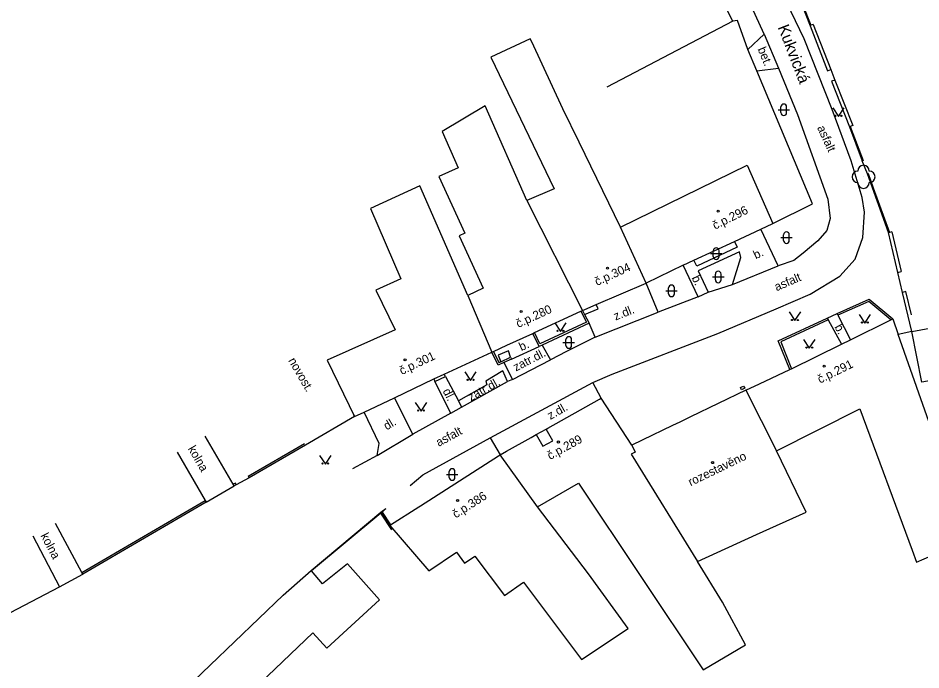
# Model space of a CAD drawing. Extents: x -577457 to -568404, y -1208466 to -1201387.
# Drawn here: x -573550.3 to -573471.9, y -1206438 to -1206381.4 of the extents above; entities that cross this region are included whole.
import ezdxf

# ---------------------------------------------------------------- set-up
doc = ezdxf.new("R2010")
doc.units = 0
for name, color, linetype in [('BUDOVY_MĚŘ', 7, 'Continuous'), ('BUDOVY_NEMĚŘ', 7, 'Continuous'), ('NÁZVY_ULIC_TOK_SMĚR', 7, 'Continuous'), ('OBVOD_PILÍŘE', 7, 'Continuous'), ('POMOC_POPIS', 7, 'Continuous'), ('ROZHRANÍ_PLOCH', 7, 'Continuous'), ('ZELEŇ', 7, 'Continuous'), ('ZN_BUDOV', 7, 'Continuous'), ('ZN_DOPLŇKOVÉ', 7, 'Continuous'), ('ZN_KULTUR', 7, 'Continuous'), ('Č_POPIS_ORIENT', 7, 'Continuous')]:
    doc.layers.add(name, color=color, linetype=linetype)

msp = doc.modelspace()

# ---------------------------------------------------------------- linework, layer by layer
at = {"layer": 'BUDOVY_MĚŘ'}
for points in [[(-573485.78, -1206399.68), (-573484.76, -1206399.2)], [(-573491.61, -1206402.38), (-573488.08, -1206400.76)], [(-573492.54, -1206402.83), (-573495.76, -1206404.39)], [(-573500.09, -1206406.24), (-573495.76, -1206404.39)], [(-573505.44, -1206408.67), (-573501.42, -1206406.82)], [(-573501.42, -1206406.82), (-573501.27, -1206406.75)], [(-573501.27, -1206406.75), (-573501.09, -1206406.67)], [(-573477.99, -1206409.3), (-573474.51, -1206407.57)], [(-573474.51, -1206407.57), (-573474.34, -1206407.49)], [(-573474.34, -1206407.49), (-573473.87, -1206408.83)], [(-573505.6, -1206408.74), (-573505.44, -1206408.67)], [(-573509.16, -1206410.37), (-573509.01, -1206410.3)], [(-573509.01, -1206410.3), (-573507.85, -1206409.77)], [(-573483.12, -1206411.82), (-573478.78, -1206409.69)], [(-573513.29, -1206412.28), (-573509.16, -1206410.37)], [(-573483.27, -1206411.89), (-573483.12, -1206411.82)], [(-573514.2, -1206412.7), (-573513.29, -1206412.28)], [(-573517.62, -1206414.33), (-573514.2, -1206412.7)], [(-573487.1, -1206413.66), (-573485.91, -1206413.11)], [(-573487.1, -1206413.66), (-573491.91, -1206415.98)], [(-573504.29, -1206416.97), (-573499.8, -1206414.44)], [(-573499.8, -1206414.44), (-573499.65, -1206414.36)], [(-573497, -1206418.44), (-573499.65, -1206414.36)], [(-573521.1, -1206415.97), (-573520.24, -1206415.57)], [(-573521.1, -1206415.97), (-573525.34, -1206418.44)], [(-573521.18, -1206415.81), (-573521.1, -1206415.97)], [(-573492.84, -1206416.44), (-573493.47, -1206416.74)], [(-573505.3, -1206417.53), (-573504.43, -1206417.05)], [(-573505.3, -1206417.53), (-573504.74, -1206418.54), (-573503.87, -1206418.06), (-573504.43, -1206417.05)], [(-573504.43, -1206417.05), (-573504.29, -1206416.97)], [(-573531.63, -1206421.84), (-573534.06, -1206417.66)], [(-573505.75, -1206417.78), (-573505.3, -1206417.53)], [(-573496.11, -1206418.01), (-573497, -1206418.44)], [(-573536.48, -1206419.06), (-573534.06, -1206423.24)], [(-573515.35, -1206423.71), (-573508.57, -1206419.36)], [(-573508.57, -1206419.36), (-573508.43, -1206419.27)], [(-573508.43, -1206419.27), (-573507.88, -1206418.96)], [(-573533.97, -1206423.39), (-573531.55, -1206421.98)], [(-573531.55, -1206421.98), (-573531.63, -1206421.84)], [(-573534.06, -1206423.24), (-573533.97, -1206423.39)], [(-573517.97, -1206425.37), (-573515.49, -1206423.8)], [(-573515.49, -1206423.8), (-573515.35, -1206423.71)], [(-573544.76, -1206429.49), (-573547.06, -1206425.25)], [(-573518.03, -1206425.41), (-573517.97, -1206425.37)], [(-573549.03, -1206426.31), (-573546.72, -1206430.75)], [(-573546.72, -1206430.75), (-573544.68, -1206429.64)], [(-573544.68, -1206429.64), (-573544.76, -1206429.49)], [(-573537.86, -1206441.6), (-573527.29, -1206431.47), (-573524.86, -1206429.31)], [(-573524.86, -1206429.31), (-573524.81, -1206429.36)], [(-573552.28, -1206433.52), (-573552.22, -1206433.61), (-573546.72, -1206430.75)]]:
    msp.add_lwpolyline(points, dxfattribs=at)
at = {"layer": 'BUDOVY_NEMĚŘ'}
for points in [[(-573497.97, -1206399.52), (-573501.57, -1206392.15), (-573502.99, -1206389.25), (-573505.69, -1206383.44), (-573505.82, -1206383.17), (-573509.26, -1206384.76), (-573503.74, -1206396.2), (-573506.13, -1206397.22)], [(-573506.13, -1206397.22), (-573509.74, -1206389), (-573513.48, -1206391.22), (-573512.08, -1206394.36), (-573513.76, -1206395.13), (-573511.51, -1206400.04), (-573512.01, -1206400.27), (-573509.9, -1206404.82), (-573511.24, -1206405.45)], [(-573497.97, -1206399.52), (-573486.98, -1206394.15), (-573484.76, -1206399.2)], [(-573511.24, -1206405.45), (-573515.42, -1206395.93), (-573519.71, -1206397.9), (-573517.05, -1206404), (-573519.23, -1206405), (-573517.55, -1206408.44), (-573523.47, -1206411.08)], [(-573506.13, -1206397.22), (-573501.27, -1206406.75)], [(-573495.76, -1206404.39), (-573497.97, -1206399.52)], [(-573446.25, -1206413.56), (-573446.89, -1206409.11), (-573461.2, -1206411.61), (-573461.32, -1206411.12), (-573471.82, -1206412.98), (-573472.69, -1206408.57), (-573447.18, -1206403.86), (-573442.02, -1206402.96)], [(-573511.24, -1206405.45), (-573509.16, -1206410.37)], [(-573484.44, -1206418.94), (-573477.18, -1206415.29), (-573472.66, -1206427.55), (-573472.28, -1206428.59), (-573467.61, -1206426.58), (-573473.87, -1206408.83)], [(-573523.47, -1206411.08), (-573521.1, -1206415.97)], [(-573487.1, -1206413.66), (-573484.44, -1206418.94)], [(-573497, -1206418.44), (-573496.72, -1206419.04), (-573497.05, -1206419.23), (-573491.3, -1206428.54), (-573486.17, -1206426.21), (-573481.85, -1206424.25), (-573484.44, -1206418.94)], [(-573505.2, -1206423.81), (-573508.43, -1206419.27)], [(-573505.2, -1206423.81), (-573501.64, -1206421.74), (-573490.81, -1206437.95), (-573487.13, -1206435.79), (-573489.12, -1206432.07), (-573491.3, -1206428.54)], [(-573518.03, -1206425.41), (-573514.64, -1206429.35), (-573512.24, -1206427.74), (-573511.54, -1206428.7), (-573510.64, -1206428.08), (-573508.06, -1206431.5), (-573506.41, -1206430.34), (-573501.37, -1206437.06), (-573497.33, -1206434.35), (-573500.75, -1206429.61), (-573505.2, -1206423.81)], [(-573530.07, -1206444.4), (-573531.25, -1206443.69), (-573532.36, -1206445.02), (-573533.85, -1206443.46), (-573524.72, -1206434.74), (-573523.5, -1206436.08), (-573518.91, -1206431.87), (-573521.71, -1206428.75), (-573523.86, -1206430.48), (-573524.81, -1206429.36)]]:
    msp.add_lwpolyline(points, dxfattribs=at)
at = {"layer": 'OBVOD_PILÍŘE'}
msp.add_lwpolyline([(-573487.43, -1206413.38), (-573487.29, -1206413.31), (-573487.19, -1206413.51), (-573487.48, -1206413.65), (-573487.57, -1206413.45), (-573487.43, -1206413.38)], dxfattribs=at)
at = {"layer": 'ROZHRANÍ_PLOCH'}
for points in [[(-573485.5, -1206382.76), (-573488.17, -1206376.93), (-573490.3, -1206372.55), (-573491.52, -1206369.72)], [(-573476.78, -1206398.23), (-573476.98, -1206396.94), (-573477.94, -1206393.75), (-573479.61, -1206389.32), (-573482.04, -1206383.18), (-573485.38, -1206376.18), (-573487.47, -1206370.94), (-573487.87, -1206370.34)], [(-573482.85, -1206378.62), (-573481.52, -1206382.03)], [(-573481.46, -1206382), (-573481.52, -1206382.03)], [(-573481.52, -1206382.03), (-573480, -1206385.95), (-573479.72, -1206385.84)], [(-573481.24, -1206381.92), (-573481.46, -1206382)], [(-573486.91, -1206384.11), (-573485.5, -1206382.76)], [(-573485.5, -1206382.76), (-573484.26, -1206385.73)], [(-573486.15, -1206385.96), (-573484.26, -1206385.73)], [(-573484.26, -1206385.73), (-573482.61, -1206389.74), (-573479.96, -1206397.1), (-573479.77, -1206398.76), (-573480.07, -1206399.8)], [(-573479.72, -1206385.84), (-573479.37, -1206386.75)], [(-573479.37, -1206386.75), (-573479.65, -1206386.86), (-573478.08, -1206390.81)], [(-573477.8, -1206390.69), (-573478.02, -1206390.78)], [(-573478.02, -1206390.78), (-573478.08, -1206390.81)], [(-573478.08, -1206390.81), (-573476.98, -1206393.75)], [(-573476.91, -1206393.72), (-573476.98, -1206393.75)], [(-573476.54, -1206394.88), (-573476.98, -1206393.75)], [(-573476.48, -1206394.86), (-573476.54, -1206394.88)], [(-573474.69, -1206399.99), (-573476.54, -1206394.88)], [(-573489.53, -1206408.75), (-573484.46, -1206406.62), (-573481.52, -1206405.35), (-573478.94, -1206403.76), (-573477.6, -1206402.29), (-573476.94, -1206400.42), (-573476.78, -1206398.23)], [(-573484.3, -1206402.88), (-573485.78, -1206399.68)], [(-573480.07, -1206399.8), (-573480.83, -1206400.71), (-573482.12, -1206401.79), (-573482.94, -1206402.42), (-573484.3, -1206402.88)], [(-573474.62, -1206399.97), (-573474.69, -1206399.99)], [(-573473.88, -1206403.45), (-573474.69, -1206399.99)], [(-573474.4, -1206399.92), (-573474.62, -1206399.97)], [(-573488.08, -1206400.76), (-573487.84, -1206401.27), (-573491.36, -1206402.91), (-573491.61, -1206402.38)], [(-573488.24, -1206404.51), (-573487.52, -1206402.15), (-573487.66, -1206401.66), (-573491.24, -1206403.3), (-573490.37, -1206405.16)], [(-573491.25, -1206405.56), (-573492.54, -1206402.83)], [(-573488.24, -1206404.51), (-573484.3, -1206402.88)], [(-573473.88, -1206403.45), (-573473.59, -1206403.38)], [(-573494.72, -1206406.89), (-573495.76, -1206404.39)], [(-573490.37, -1206405.16), (-573488.24, -1206404.51)], [(-573491.25, -1206405.56), (-573494.72, -1206406.89)], [(-573491.25, -1206405.56), (-573490.37, -1206405.16)], [(-573472.7, -1206407.12), (-573473.21, -1206405.11), (-573473.5, -1206405.18)], [(-573472.69, -1206408.57), (-573473.5, -1206405.18)], [(-573479.16, -1206407.02), (-573476.38, -1206405.76), (-573474.34, -1206407.49)], [(-573474.51, -1206407.57), (-573476.41, -1206405.96), (-573479.09, -1206407.17)], [(-573501.42, -1206406.82), (-573500.94, -1206407.78), (-573504.98, -1206409.65), (-573505.44, -1206408.67)], [(-573501.27, -1206406.75), (-573501.1, -1206407.09)], [(-573501.1, -1206407.09), (-573500.71, -1206407.86)], [(-573500.19, -1206409.06), (-573494.72, -1206406.89)], [(-573480.02, -1206407.41), (-573479.16, -1206407.02)], [(-573479.09, -1206407.17), (-573479.16, -1206407.02)], [(-573500.71, -1206407.86), (-573504.8, -1206409.75)], [(-573500.19, -1206409.06), (-573500.71, -1206407.86)], [(-573483.27, -1206411.89), (-573484.29, -1206409.38), (-573480.02, -1206407.41)], [(-573479.95, -1206407.56), (-573484.07, -1206409.47), (-573483.12, -1206411.82)], [(-573480.02, -1206407.41), (-573479.95, -1206407.56)], [(-573479.95, -1206407.56), (-573478.78, -1206409.69)], [(-573479.09, -1206407.17), (-573477.99, -1206409.3)], [(-573505.06, -1206409.87), (-573505.6, -1206408.74)], [(-573500.19, -1206409.06), (-573502.67, -1206410.32), (-573504.07, -1206411.04)], [(-573498.72, -1206412.28), (-573489.53, -1206408.75)], [(-573509.01, -1206410.3), (-573508.54, -1206411.28), (-573508.38, -1206411.21)], [(-573507.53, -1206410.81), (-573507.7, -1206410.26), (-573508.62, -1206410.64), (-573508.38, -1206411.21)], [(-573507.46, -1206410.97), (-573505.06, -1206409.87)], [(-573504.8, -1206409.75), (-573505.06, -1206409.87)], [(-573504.8, -1206409.75), (-573504.07, -1206411.04)], [(-573508.12, -1206411.27), (-573508.62, -1206411.5), (-573509.16, -1206410.37)], [(-573508.38, -1206411.21), (-573507.53, -1206410.81), (-573507.46, -1206410.97)], [(-573507.46, -1206410.97), (-573508.12, -1206411.27)], [(-573507.37, -1206412.75), (-573504.07, -1206411.04)], [(-573508.12, -1206411.27), (-573507.37, -1206412.75)], [(-573514.2, -1206412.7), (-573514.11, -1206412.91), (-573513.19, -1206412.49), (-573513.29, -1206412.28)], [(-573513.19, -1206412.49), (-573512.06, -1206414.59)], [(-573507.8, -1206412.92), (-573508.21, -1206412), (-573509.68, -1206412.88), (-573509.58, -1206413.2), (-573512.06, -1206414.59)], [(-573500.4, -1206413), (-573498.72, -1206412.28)], [(-573512.73, -1206415.68), (-573514.11, -1206412.91)], [(-573511.79, -1206415.14), (-573507.8, -1206412.92)], [(-573509.3, -1206417.81), (-573500.4, -1206413)], [(-573507.37, -1206412.75), (-573507.8, -1206412.92)], [(-573499.65, -1206414.36), (-573500.4, -1206413)], [(-573516.01, -1206417.48), (-573517.62, -1206414.33)], [(-573512.06, -1206414.59), (-573511.79, -1206415.14)], [(-573519.13, -1206419.35), (-573518.95, -1206418.31), (-573520.24, -1206415.57)], [(-573512.73, -1206415.68), (-573516.01, -1206417.48)], [(-573512.73, -1206415.68), (-573511.79, -1206415.14)], [(-573519.13, -1206419.35), (-573516.01, -1206417.48)], [(-573516.26, -1206421.95), (-573515.14, -1206421.02), (-573509.3, -1206417.81)], [(-573509.3, -1206417.81), (-573508.43, -1206419.27)], [(-573525.34, -1206418.44), (-573530.23, -1206421.29)], [(-573519.13, -1206419.35), (-573521.26, -1206420.5)], [(-573530.32, -1206421.14), (-573530.23, -1206421.29)], [(-573531.36, -1206421.88), (-573531.44, -1206421.73), (-573531.63, -1206421.84)], [(-573531.36, -1206421.88), (-573531.55, -1206421.98)], [(-573530.23, -1206421.29), (-573531.36, -1206421.88)], [(-573533.97, -1206423.39), (-573544.68, -1206429.64)], [(-573524.86, -1206429.31), (-573518.79, -1206424.26)], [(-573518.79, -1206424.26), (-573518.38, -1206423.93)], [(-573518.79, -1206424.26), (-573518.03, -1206425.41)], [(-573518.38, -1206423.93), (-573518.7, -1206424.27), (-573517.97, -1206425.37)]]:
    msp.add_lwpolyline(points, dxfattribs=at)
at = {"layer": 'ZELEŇ'}
msp.add_circle((-573476.87, -1206395.15), 0.0005, dxfattribs=at)
for centre, start, end in [((-573476.87, -1206394.65), 0, 179.99999), ((-573477.37, -1206395.15), 89.99999, 269.99999), ((-573476.37, -1206395.15), 270, 89.99999), ((-573476.87, -1206395.65), 179.99999, 359.99999)]:
    msp.add_arc(centre, 0.5, start, end, dxfattribs=at)
at = {"layer": 'ZN_BUDOV'}
for centre in [(-573489.49, -1206398.13), (-573499.11, -1206403.08), (-573506.62, -1206406.85), (-573516.7, -1206411.03), (-573480.3, -1206411.59), (-573503.38, -1206418.17), (-573489.98, -1206419.96), (-573512.13, -1206423.24)]:
    msp.add_circle(centre, 0.0875, dxfattribs=at)
at = {"layer": 'ZN_DOPLŇKOVÉ'}
for points in [[(-573488.22, -1206381.65), (-573489.93, -1206378.25)], [(-573482.78, -1206378.59), (-573481.46, -1206382)], [(-573488.22, -1206381.65), (-573499.18, -1206387.36)], [(-573486.91, -1206384.11), (-573487.83, -1206381.57), (-573488.22, -1206381.65)], [(-573481.24, -1206381.92), (-573479.72, -1206385.84)], [(-573486.15, -1206385.96), (-573486.91, -1206384.11)], [(-573481.31, -1206397.5), (-573486.15, -1206385.96)], [(-573479.37, -1206386.75), (-573477.8, -1206390.69)], [(-573478.02, -1206390.78), (-573476.91, -1206393.72)], [(-573476.48, -1206394.86), (-573476.03, -1206396.1), (-573474.62, -1206399.97)], [(-573484.76, -1206399.2), (-573481.31, -1206397.5)], [(-573488.08, -1206400.76), (-573485.78, -1206399.68)], [(-573474.4, -1206399.92), (-573473.59, -1206403.38)], [(-573492.54, -1206402.83), (-573491.61, -1206402.38)], [(-573473.5, -1206405.18), (-573473.88, -1206403.45)], [(-573501.1, -1206407.09), (-573499.91, -1206406.61), (-573500.09, -1206406.24)], [(-573501.09, -1206406.67), (-573500.09, -1206406.24)], [(-573472.69, -1206408.57), (-573473.87, -1206408.83)], [(-573507.85, -1206409.77), (-573505.6, -1206408.74)], [(-573478.78, -1206409.69), (-573477.99, -1206409.3)], [(-573485.91, -1206413.11), (-573483.27, -1206411.89)], [(-573520.24, -1206415.57), (-573517.62, -1206414.33)], [(-573491.91, -1206415.98), (-573492.84, -1206416.44)], [(-573493.47, -1206416.74), (-573496.11, -1206418.01)], [(-573507.88, -1206418.96), (-573505.75, -1206417.78)], [(-573530.32, -1206421.14), (-573525.43, -1206418.29)], [(-573544.76, -1206429.49), (-573534.06, -1206423.24)], [(-573517.86, -1206425.8), (-573518.8, -1206424.36), (-573524.81, -1206429.36)]]:
    msp.add_lwpolyline(points, dxfattribs=at)
at = {"layer": 'ZN_KULTUR'}
for p, q in [((-573484.05, -1206389.58), (-573484.05, -1206389.08)), ((-573483.55, -1206389.58), (-573483.55, -1206389.08)), ((-573484.3, -1206389.33), (-573483.3, -1206389.33)), ((-573484.07, -1206400.43), (-573483.07, -1206400.43)), ((-573483.82, -1206400.68), (-573483.82, -1206400.18)), ((-573483.32, -1206400.68), (-573483.32, -1206400.18)), ((-573489.92, -1206402.07), (-573489.92, -1206401.57)), ((-573489.42, -1206402.07), (-573489.42, -1206401.57)), ((-573490.17, -1206401.82), (-573489.17, -1206401.82)), ((-573489.99, -1206403.84), (-573488.99, -1206403.84)), ((-573489.74, -1206404.09), (-573489.74, -1206403.59)), ((-573489.24, -1206404.09), (-573489.24, -1206403.59)), ((-573493.8, -1206405.3), (-573493.8, -1206404.8)), ((-573493.3, -1206405.3), (-573493.3, -1206404.8)), ((-573494.05, -1206405.05), (-573493.05, -1206405.05)), ((-573502.73, -1206409.78), (-573502.73, -1206409.28)), ((-573502.23, -1206409.78), (-573502.23, -1206409.28)), ((-573502.98, -1206409.53), (-573501.98, -1206409.53)), ((-573513.11, -1206420.99), (-573512.11, -1206420.99)), ((-573512.86, -1206421.24), (-573512.86, -1206420.74)), ((-573512.36, -1206421.24), (-573512.36, -1206420.74))]:
    msp.add_line(p, q, dxfattribs=at)
for points in [[(-573479.55, -1206389.16), (-573479.05, -1206389.91), (-573478.55, -1206389.16)], [(-573483.33, -1206406.88), (-573482.83, -1206407.63), (-573482.33, -1206406.88)], [(-573477.26, -1206407.1), (-573476.76, -1206407.85), (-573476.26, -1206407.1)], [(-573503.7, -1206407.82), (-573503.2, -1206408.57), (-573502.7, -1206407.82)], [(-573482.08, -1206409.28), (-573481.58, -1206410.03), (-573481.08, -1206409.28)], [(-573511.51, -1206412.07), (-573511.01, -1206412.82), (-573510.51, -1206412.07)], [(-573515.81, -1206414.74), (-573515.31, -1206415.49), (-573514.81, -1206414.74)], [(-573524.12, -1206419.34), (-573523.62, -1206420.09), (-573523.12, -1206419.34)]]:
    msp.add_lwpolyline(points, dxfattribs=at)
for centre in [(-573479.3, -1206389.86), (-573478.8, -1206389.86), (-573483.08, -1206407.58), (-573482.58, -1206407.58), (-573477.01, -1206407.8), (-573476.51, -1206407.8), (-573503.45, -1206408.52), (-573502.95, -1206408.52), (-573481.83, -1206409.98), (-573481.33, -1206409.98), (-573511.26, -1206412.77), (-573510.76, -1206412.77), (-573515.56, -1206415.44), (-573515.06, -1206415.44), (-573523.87, -1206420.04), (-573523.37, -1206420.04)]:
    msp.add_circle(centre, 0.05, dxfattribs=at)
for centre, start, end in [((-573483.8, -1206389.08), 0, 179.99999), ((-573483.8, -1206389.58), 179.99999, 359.99999), ((-573483.57, -1206400.18), 0, 179.99999), ((-573483.57, -1206400.68), 179.99999, 359.99999), ((-573489.67, -1206401.57), 0, 179.99999), ((-573489.67, -1206402.07), 179.99999, 359.99999), ((-573489.49, -1206403.59), 0, 179.99999), ((-573493.55, -1206404.8), 0, 179.99999), ((-573489.49, -1206404.09), 179.99999, 359.99999), ((-573493.55, -1206405.3), 179.99999, 359.99999), ((-573502.48, -1206409.28), 0, 179.99999), ((-573502.48, -1206409.78), 179.99999, 359.99999), ((-573512.61, -1206420.74), 0, 179.99999), ((-573512.61, -1206421.24), 179.99999, 359.99999)]:
    msp.add_arc(centre, 0.25, start, end, dxfattribs=at)

# ---------------------------------------------------------------- texts
at = {"layer": 'NÁZVY_ULIC_TOK_SMĚR'}
msp.add_text('Kukvická', height=1, rotation=291.11, dxfattribs=at).set_placement((-573484.34, -1206382.16))
at = {"layer": 'POMOC_POPIS'}
for s, rotation, p in [('bet.', 292.66094, (-573486.09, -1206384.06)), ('asfalt', 294.60665, (-573480.92, -1206390.88)), ('b.', 25.76454, (-573486.23, -1206402.32)), ('b.', 295.29202, (-573491.82, -1206403.91)), ('asfalt', 23.36304, (-573484.42, -1206405.09)), ('z.dl.', 21.63867, (-573498.41, -1206407.63)), ('b.', 298.77979, (-573479.42, -1206408.18)), ('b.', 24.62355, (-573506.6, -1206410.29)), ('zatr.dl.', 27.39237, (-573507.07, -1206412.06)), ('novost.', 300.23, (-573526.87, -1206411.1)), ('zatr.dl.', 29.09119, (-573510.98, -1206414.65)), ('dl.', 296.48228, (-573513.45, -1206413.74)), ('z.dl.', 29.40013, (-573504.08, -1206416.26)), ('dl.', 30.93674, (-573518.29, -1206417.17)), ('asfalt', 28.79571, (-573513.77, -1206418.6)), ('kolna', 300.15001, (-573535.59, -1206418.75)), ('rozestavěno', 25.74935, (-573491.89, -1206422.02)), ('kolna', 297.50003, (-573548.38, -1206426.29))]:
    msp.add_text(s, height=0.75, rotation=rotation, dxfattribs=at).set_placement(p)
at = {"layer": 'Č_POPIS_ORIENT'}
for s, rotation, p in [('č.p.296', 26.36998, (-573489.77, -1206399.75)), ('č.p.304', 24.65002, (-573500.02, -1206404.63)), ('č.p.280', 24.77, (-573506.86, -1206408.28)), ('č.p.301', 25.33001, (-573516.98, -1206412.36)), ('č.p.291', 26.23998, (-573480.65, -1206413.11)), ('č.p.289', 29.01, (-573504.1, -1206419.74)), ('č.p.386', 32.67, (-573512.29, -1206424.82))]:
    msp.add_text(s, height=0.75, rotation=rotation, dxfattribs=at).set_placement(p)

doc.saveas('drawing.dxf')
